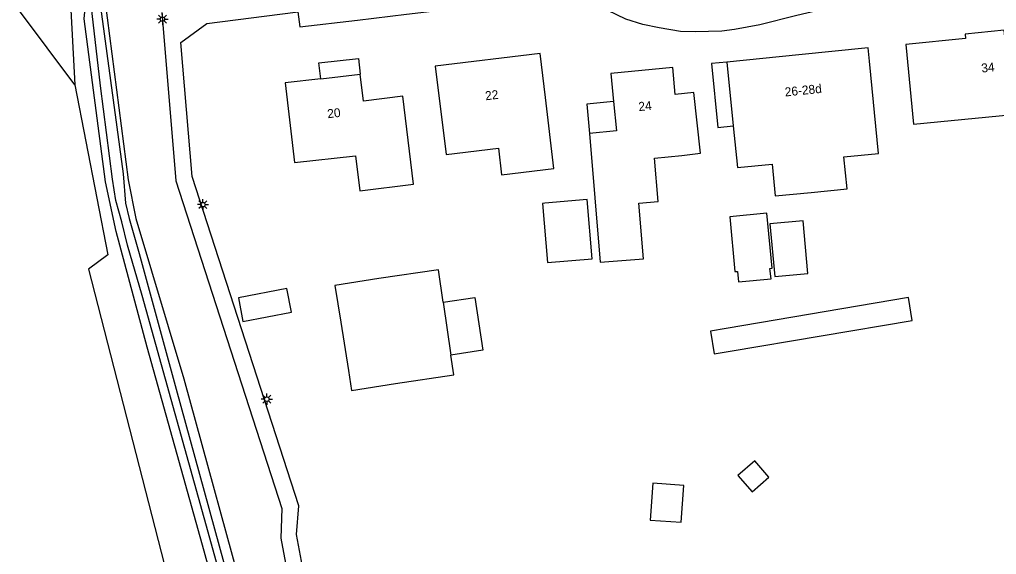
# Model space of a CAD drawing. Extents: x 140000 to 143000, y 403500 to 406000.
# Drawn here: x 140390.1 to 140499.7, y 403614.1 to 403674.1 of the extents above; entities that cross this region are included whole.
import ezdxf

# ---------------------------------------------------------------- set-up
doc = ezdxf.new("R2010")
doc.units = 0
for name, color, linetype in [('gg-anno-huisnummerreeks BGT', 7, 'Continuous'), ('gg-bbg-bijgebouw', 7, 'Continuous'), ('gg-bbg-hoofdgebouw', 7, 'Continuous'), ('gg-bbg-luifel en loopbrug', 7, 'Continuous'), ('gg-bbg-overig bouwwerk', 7, 'Continuous'), ('gg-knt-verharding', 7, 'Continuous'), ('gg-kntw-bovenkant insteek waterloop', 7, 'Continuous'), ('gg-kntw-waterlijn', 7, 'Continuous'), ('gt-grn-groengrens', 7, 'Continuous'), ('gt-symb-lichtmast', 7, 'Continuous')]:
    doc.layers.add(name, color=color, linetype=linetype)

# ---------------------------------------------------------------- blocks, each defined once
blk = doc.blocks.new('gt0-LMAST')
at = {"layer": 'gt-symb-lichtmast'}
for p, q in [((-0.18, 0.17), (-0.45, 0.44)), ((-0.01, 0.25), (-0.01, 0.62)), ((0.17, 0.17), (0.44, 0.44)), ((-0.26, 0), (-0.63, 0)), ((-0.18, -0.18), (-0.45, -0.45)), ((-0.01, -0.25), (-0.01, -0.63)), ((0.44, -0.45), (0.17, -0.18)), ((0.24, 0), (0.62, 0))]:
    blk.add_line(p, q, dxfattribs=at)
blk.add_circle((-0.01, 0), 0.25, dxfattribs=at)

msp = doc.modelspace()

# ---------------------------------------------------------------- linework, layer by layer
at = {"layer": 'gg-bbg-bijgebouw'}
msp.add_line((140437.64, 403642.39), (140438.51, 403636.45), dxfattribs=at)
for points in [[(140449.06, 403653.48), (140448.79, 403653.46), (140449.35, 403646.82), (140454.35, 403647.24), (140453.8, 403653.9), (140449.06, 403653.48)], [(140473.95, 403652.36), (140469.78, 403651.96), (140470.37, 403645.8), (140470.65, 403645.82), (140470.76, 403644.66), (140474.41, 403645), (140474.27, 403646.17), (140474.54, 403646.2), (140473.95, 403652.36)], [(140437.64, 403642.39), (140437.11, 403646), (140430.42, 403645.02), (140425.49, 403644.23), (140426.15, 403640.14), (140427.01, 403634.7), (140427.37, 403632.47), (140432.3, 403633.25), (140438.84, 403634.21), (140438.51, 403636.45)], [(140489.82, 403642.9), (140469.39, 403639.44), (140467.62, 403639.14), (140468.05, 403636.58), (140469.82, 403636.88), (140490.26, 403640.34), (140489.82, 403642.9)]]:
    msp.add_lwpolyline(points, dxfattribs=at)
at = {"layer": 'gg-bbg-hoofdgebouw'}
for p, q in [((140469.47, 403669.31), (140470.18, 403662.15)), ((140423.91, 403667.45), (140428.33, 403667.94))]:
    msp.add_line(p, q, dxfattribs=at)
for points in [[(140500.99, 403668.85), (140500.56, 403672.91), (140496.17, 403672.46), (140496.23, 403671.96), (140489.53, 403671.3), (140490.4, 403662.35), (140501.52, 403663.43), (140501.47, 403663.9)], [(140436.76, 403668.86), (140437.96, 403658.95), (140443.85, 403659.65), (140444.2, 403656.68), (140450.06, 403657.38), (140449.11, 403665.32), (140448.51, 403670.29), (140436.76, 403668.86)], [(140470.18, 403662.15), (140470.65, 403657.49), (140474.53, 403657.87), (140474.89, 403654.29), (140478.92, 403654.69), (140482.94, 403655.08), (140482.59, 403658.67), (140486.47, 403659.05), (140485.45, 403669.42), (140485.3, 403670.9), (140477.53, 403670.12), (140469.47, 403669.31)], [(140423.91, 403667.45), (140419.9, 403667), (140420.96, 403658.05), (140427.79, 403658.81), (140428.28, 403654.86), (140434.3, 403655.6), (140433.13, 403665.48), (140428.7, 403664.93), (140428.33, 403667.94)], [(140454.04, 403661.31), (140455.23, 403646.85), (140460.11, 403647.25), (140459.6, 403653.48), (140461.74, 403653.66), (140461.35, 403658.52), (140464.39, 403658.85), (140466.5, 403659.09), (140465.75, 403665.89), (140463.67, 403665.69), (140463.4, 403668.7), (140456.44, 403668.02), (140456.75, 403664.9)], [(140456.75, 403664.9), (140457.07, 403661.61), (140454.04, 403661.31)]]:
    msp.add_lwpolyline(points, dxfattribs=at)
at = {"layer": 'gg-bbg-luifel en loopbrug'}
for points in [[(140423.91, 403667.45), (140423.71, 403669.24), (140428.13, 403669.73), (140428.33, 403667.94)], [(140469.47, 403669.31), (140467.73, 403669.14), (140468.44, 403661.97), (140470.18, 403662.15)], [(140456.75, 403664.9), (140453.77, 403664.6), (140454.04, 403661.31)], [(140474.82, 403645.25), (140478.55, 403645.59), (140478.01, 403651.5), (140474.28, 403651.16), (140474.82, 403645.25)], [(140437.64, 403642.39), (140441.2, 403642.91), (140442.07, 403636.98), (140438.51, 403636.45)]]:
    msp.add_lwpolyline(points, dxfattribs=at)
at = {"layer": 'gg-bbg-overig bouwwerk'}
for points in [[(140415.18, 403640.21), (140420.62, 403641.26), (140420.1, 403643.92), (140414.67, 403642.86), (140415.18, 403640.21)], [(140472.28, 403621.11), (140474.18, 403622.75), (140472.6, 403624.58), (140470.7, 403622.93), (140472.28, 403621.11)], [(140464.63, 403621.82), (140461.15, 403622.07), (140460.86, 403617.94), (140464.35, 403617.7), (140464.63, 403621.82)]]:
    msp.add_lwpolyline(points, dxfattribs=at)
at = {"layer": 'gg-knt-verharding'}
for points in [[(140524.21, 403683.93), (140516.47, 403683.08), (140510.75, 403682.4), (140506.71, 403681.55), (140493.14, 403678.26), (140477.3, 403674.53), (140473.16, 403673.49), (140470.33, 403672.95), (140468.88, 403672.77), (140465.91, 403672.71), (140464.27, 403672.75), (140461.87, 403673.14), (140460.02, 403673.53), (140458.13, 403674.14), (140456.09, 403675.09), (140454.28, 403676.02), (140452.91, 403676.9), (140452.21, 403677.54)], [(140421.06, 403674.9), (140421.35, 403674.93), (140421.56, 403673.25), (140428.02, 403674.03), (140433.53, 403674.69), (140451.73, 403676.87), (140452.21, 403677.54)], [(140406.1, 403674.88), (140407.67, 403655.99), (140419.56, 403619.22), (140419.42, 403615.9), (140420.91, 403607.91)], [(140428.35, 403580.45), (140426.79, 403594.18), (140424.99, 403595.96), (140421.18, 403616.33), (140421.45, 403619.53), (140409.47, 403656.48), (140408.2, 403671.5), (140411.12, 403673.65), (140421.06, 403674.9)]]:
    msp.add_lwpolyline(points, dxfattribs=at)
at = {"layer": 'gg-kntw-bovenkant insteek waterloop'}
msp.add_lwpolyline([(140420.85, 403578.21), (140419.47, 403583.11), (140410.65, 403615.1), (140404.44, 403637.32), (140400.95, 403650.31), (140399.75, 403655.87), (140397.36, 403674.15), (140397.48, 403675.34), (140397.93, 403676.05), (140398.38, 403676.52), (140398.92, 403676.79), (140399.36, 403676.66), (140399.71, 403676.32), (140402.3, 403656.1), (140403.18, 403651.75), (140408.57, 403633.77), (140416, 403606.64)], dxfattribs=at)
at = {"layer": 'gg-kntw-waterlijn'}
msp.add_lwpolyline([(140422.01, 403578.25), (140417.19, 403595.3), (140411.3, 403616.57), (140403.88, 403643.13), (140402.24, 403648.78), (140401.59, 403651.4), (140400.92, 403653.77), (140400.54, 403656.18), (140399.22, 403666.63), (140398.15, 403675.74), (140398.28, 403675.87), (140398.58, 403676.02), (140399.06, 403675.86), (140399.21, 403675.52), (140401.74, 403656.78), (140402, 403653.48), (140402.42, 403651.77), (140403.56, 403647.85), (140407.7, 403632.6), (140415.15, 403605.49), (140421.14, 403584.7), (140422.89, 403578.51)], dxfattribs=at)
at = {"layer": 'gt-grn-groengrens'}
for p, q in [((140394.31, 403704.68), (140396.32, 403666.76)), ((140396.32, 403666.76), (140390.13, 403675.07))]:
    msp.add_line(p, q, dxfattribs=at)
msp.add_lwpolyline([(140396.32, 403666.76), (140400.02, 403647.69), (140397.86, 403646.07), (140414.17, 403582.59), (140417.82, 403568.41), (140407.9, 403548.67)], dxfattribs=at)

# ---------------------------------------------------------------- block references
at = {"layer": 'gt-symb-lichtmast'}
for p in [(140406.16, 403674.13), (140410.7, 403653.32), (140417.87, 403631.5)]:
    msp.add_blockref('gt0-LMAST', p, dxfattribs=at)

# ---------------------------------------------------------------- texts
at = {"layer": 'gg-anno-huisnummerreeks BGT'}
for s, rotation, p in [('34', 5.8, (140498.05, 403668.13)), ('26-28d', 5.7, (140476, 403665.45)), ('22', 6.9, (140442.41, 403665.02)), ('24', 5.6, (140459.59, 403663.81)), ('20', 6.3, (140424.7, 403663.01))]:
    msp.add_text(s, height=1, rotation=rotation, dxfattribs=at).set_placement(p)

doc.saveas('drawing.dxf')
